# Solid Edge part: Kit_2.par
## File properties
Author: bmolnar
Last saved by: bmolnar
Revision: 77
Sűrűség: 0,000 kg/m^3
Pontosság: 0,990
Username: bmolnar
Dokumentum tartalom típus: 0
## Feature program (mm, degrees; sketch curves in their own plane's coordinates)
base feature "unnamed BaseFeature 1"
sketch for "Furat_1" plane through (-18.15, -81.65, 0) normal (1, 0, 0) x-axis (0, 0, -1)
  hole centre (0, 13.85) bore radius 2.067
hole "Furat_1" nominal diameter 5 finite  ThreadDepth = 5 mm; StartChamferOffset = 0.6 mm; StartChamferAngle = 45 deg
sketch for "Furat_2" plane through (-11, -70.2, -11) normal (0, -1, 0) x-axis (0, 0, 1)
  hole centre (0, 0) bore radius 2.067
hole "Furat_2" nominal diameter 5
sketch for "unnamed Hole 1" plane through (-11, -70.2, -11) normal (0, -1, 0) x-axis (0, 0, 1)
  hole centre (22, 0) bore radius 2.067
hole "unnamed Hole 1"
sketch for "unnamed Hole 2" plane through (-11, -70.2, -11) normal (0, -1, 0) x-axis (0, 0, 1)
  hole centre (22, -22) bore radius 2.067
hole "unnamed Hole 2"
sketch for "unnamed Hole 3" plane through (-11, -70.2, -11) normal (0, -1, 0) x-axis (0, 0, 1)
  hole centre (0, -22) bore radius 2.067
hole "unnamed Hole 3"
pattern "unnamed Pattern 1" of "Furat_2", "unnamed Hole 1", "unnamed Hole 2", "unnamed Hole 3"
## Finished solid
Body 1: solid body, 258 faces, 616 edges, 372 vertices, 2 internal voids.
  Faces by surface: plane 124, cylinder 58, swept 43, cone 26, torus 7
  Edges by curve: line 361, circle 155, spline 90, curve on surface 5, intersection 4, ellipse 1
Bounding box of the edges (mm; curved faces can reach further): 36.300 x 11.800 x 36.300, from (-18.15, -75.3, -18.15) to (18.15, -63.5, 18.15).
Cylindrical faces by radius (mm): R0.2 x18, R0.4307 x1, R0.4865 x1, R2.067 x5, R3.75 x2, R4 x4, R4.1 x12, R5.24 x1, R5.45 x2, R5.55 x2, R5.7 x1, R6 x1, R6.92 x1, R7 x1, R11.25 x6
Conical faces (half-angle, radius in mm at the cone's reference point): 0.5 deg R4.5 x4, 3 deg R6.96 x1, 7 deg R6.4156 x1, 14 deg R5.12 x1, 14 deg R5.3801 x1, 17 deg R5.12 x1, 23 deg R5.7369 x1, 42.5 deg R5.1096 x1, 45 deg R2.317 x2, 45 deg R2.367 x2, 45 deg R2.667 x1, 45 deg R4.25 x2, 45 deg R5.3 x2, 45 deg R5.35 x2, 45 deg R5.85 x1, 84 deg R5.4096 x1, 85 deg R6.73 x1, 87 deg R5.1371 x1
Toroidal faces (ring radius, tube radius in mm): R3.8 r0.2 x2, R4.4 r0.4 x2, R5.6606 r0.18 x1, R6.1131 r0.26 x1, R6.72 r0.2 x1
Planar faces by outward normal: +x 5, +y 4, +z 15, -x 7, -y 16, -z 13, oblique 64
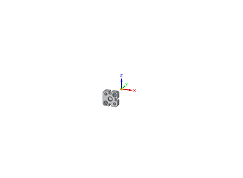
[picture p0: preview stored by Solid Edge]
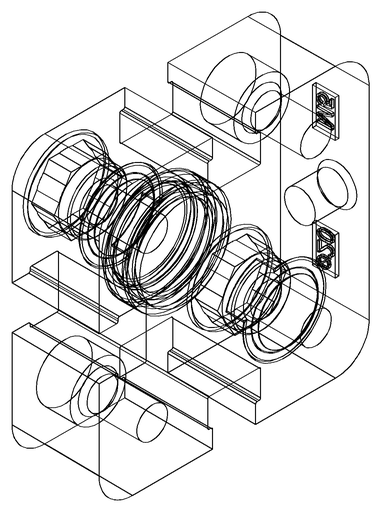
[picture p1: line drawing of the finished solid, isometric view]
